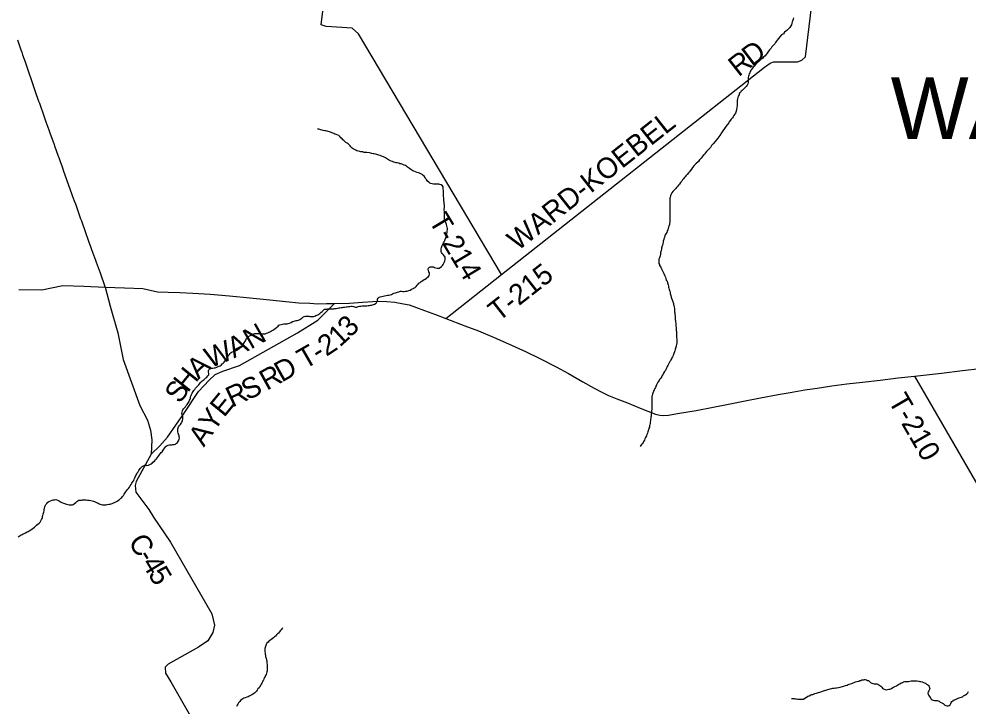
# Model space of a CAD drawing. Extents: x 1310247 to 1664935, y 284496 to 704931.
# Drawn here: x 1521928 to 1535762, y 510674 to 520692 of the extents above; entities that cross this region are included whole.
import ezdxf

# ---------------------------------------------------------------- set-up
doc = ezdxf.new("R2010")
doc.units = 0
for name, color, linetype in [('GM_X_Airport_Location_Class_2', 7, 'Continuous'), ('GM_X_County_Road_Text', 7, 'Continuous'), ('GM_X_County_Subdivision_Text', 7, 'Continuous'), ('GM_X_Interstate_Shield', 7, 'Continuous'), ('GM_X_Minor_River_Text', 7, 'Continuous'), ('GM_X_Township_Road', 7, 'Continuous'), ('GM_X_Township_Subdivision', 7, 'Continuous')]:
    doc.layers.add(name, color=color, linetype=linetype)

msp = doc.modelspace()

# ---------------------------------------------------------------- linework, layer by layer
at = {"layer": 'GM_X_County_Road_Text'}
msp.add_lwpolyline([(1521905, 520389), (1521936, 520301), (1521956, 520244), (1521969, 520208), (1521981, 520171), (1522016, 520068), (1522027, 520037), (1522150, 519680), (1522160, 519649), (1522166, 519633), (1522214, 519493), (1522225, 519462), (1522230, 519447), (1522285, 519292), (1522305, 519236), (1522321, 519193), (1522336, 519153), (1522362, 519076), (1522379, 519029), (1522440, 518860), (1522446, 518844), (1522501, 518690), (1522507, 518674), (1522523, 518628), (1522556, 518535), (1522578, 518473), (1522694, 518148), (1522705, 518118), (1522733, 518040), (1522750, 517994), (1522766, 517950), (1522827, 517778), (1522837, 517746), (1522897, 517576), (1522936, 517468), (1522941, 517453), (1522947, 517437), (1522969, 517376), (1522975, 517360), (1522986, 517329), (1523043, 517175), (1523048, 517160), (1523054, 517145), (1523110, 516990), (1523115, 516975), (1523121, 516959), (1523126, 516944), (1523165, 516835), (1523175, 516804), (1523181, 516789), (1523183, 516781), (1523257, 516502), (1523370, 516114), (1523445, 515726), (1523691, 515057), (1523801, 514842), (1523845, 514694), (1523863, 514553), (1523854, 514345), (1523636, 513947), (1523623, 513889), (1523632, 513792), (1523820, 513538), (1523888, 513429), (1524135, 513062), (1524739, 512018), (1524778, 511851), (1524756, 511745), (1524682, 511622), (1524545, 511533), (1524103, 511284), (1524057, 511238), (1524064, 511154), (1524141, 511025), (1525122, 509309)], dxfattribs=at)
at = {"layer": 'GM_X_County_Subdivision_Text'}
for points in [[(1528152, 516326), (1528963, 516966), (1532793, 519990), (1532878, 520049), (1532928, 520068), (1533275, 520069), (1533340, 520092), (1533395, 520141), (1533719, 522838), (1533986, 524929)], [(1528963, 516966), (1526878, 520477), (1526783, 520557), (1526408, 520580), (1526332, 520608), (1526811, 524451)], [(1523854, 514345), (1523982, 514468), (1524094, 514594), (1524337, 514944), (1524547, 515258), (1524701, 515427), (1524788, 515506), (1524901, 515555), (1525144, 515640), (1525987, 516117), (1526284, 516301), (1526525, 516541)], [(1534981, 515482), (1537007, 511984), (1537078, 511898), (1537141, 511835), (1537181, 511793), (1537242, 511641), (1537603, 511101)]]:
    msp.add_lwpolyline(points, dxfattribs=at)
at = {"layer": 'GM_X_Interstate_Shield'}
msp.add_lwpolyline([(1521927, 516748), (1522263, 516741), (1522566, 516806), (1522872, 516794), (1523183, 516781), (1523464, 516773), (1523734, 516764), (1523947, 516714), (1524104, 516708), (1524272, 516705), (1524464, 516693), (1524716, 516678), (1524996, 516653), (1525291, 516626), (1525583, 516595), (1525817, 516573), (1526009, 516555), (1526169, 516546), (1526282, 516540), (1526410, 516541), (1526525, 516541), (1526748, 516548), (1526933, 516562), (1527087, 516572), (1527175, 516577), (1527287, 516572), (1527407, 516563), (1527532, 516538), (1527616, 516521), (1527708, 516490), (1527839, 516439), (1527999, 516381), (1528152, 516326), (1528427, 516219), (1528628, 516145), (1528855, 516048), (1529064, 515956), (1529313, 515844), (1529522, 515742), (1529759, 515621), (1529936, 515523), (1530145, 515399), (1530312, 515306), (1530413, 515255), (1530519, 515203), (1530642, 515154), (1530796, 515095), (1530985, 515017), (1531206, 514931), (1531268, 514914), (1531322, 514909), (1531394, 514915), (1531528, 514937), (1531798, 514985), (1532045, 515032), (1532269, 515076), (1532489, 515118), (1532738, 515167), (1532994, 515217), (1533171, 515245), (1533385, 515283), (1533563, 515309), (1533779, 515343), (1533994, 515370), (1534224, 515394), (1534482, 515426), (1534742, 515457), (1534981, 515482), (1535377, 515528), (1535683, 515565), (1535938, 515595)], dxfattribs=at)
at = {"layer": 'GM_X_Minor_River_Text'}
for points in [[(1533220, 520710), (1533213, 520688), (1533205, 520662), (1533200, 520648), (1533196, 520630), (1533187, 520604), (1533179, 520590), (1533164, 520568), (1533144, 520548), (1533119, 520525), (1533088, 520497), (1533072, 520477), (1533045, 520458), (1533020, 520432), (1532998, 520406), (1532979, 520381), (1532964, 520363), (1532954, 520349), (1532944, 520329), (1532925, 520309), (1532902, 520284), (1532890, 520268), (1532869, 520240), (1532855, 520222), (1532836, 520192), (1532821, 520175), (1532805, 520155), (1532782, 520133), (1532770, 520119), (1532743, 520100), (1532712, 520070), (1532690, 520052), (1532669, 520031), (1532646, 520003), (1532632, 519989), (1532622, 519975), (1532603, 519952), (1532595, 519938), (1532586, 519924), (1532580, 519908), (1532573, 519894), (1532565, 519870), (1532561, 519856), (1532558, 519840), (1532558, 519820), (1532557, 519798), (1532555, 519778), (1532556, 519764), (1532552, 519744), (1532543, 519726), (1532527, 519706), (1532510, 519686), (1532490, 519666), (1532471, 519651), (1532457, 519639), (1532445, 519621), (1532428, 519603), (1532426, 519587), (1532413, 519565)], [(1532413, 519565), (1532405, 519545), (1532400, 519529), (1532396, 519501), (1532395, 519473), (1532396, 519455), (1532396, 519431), (1532393, 519401), (1532387, 519371), (1532382, 519349), (1532371, 519317), (1532357, 519297), (1532348, 519283), (1532338, 519265), (1532327, 519248), (1532311, 519230), (1532298, 519214), (1532282, 519190), (1532273, 519176), (1532249, 519149), (1532232, 519123), (1532211, 519093), (1532190, 519059), (1532169, 519029), (1532142, 518992), (1532115, 518956), (1532093, 518924), (1532076, 518905), (1532047, 518873), (1532037, 518859), (1532022, 518845), (1532008, 518819), (1531987, 518800), (1531969, 518778), (1531952, 518758), (1531931, 518735), (1531919, 518717), (1531902, 518699), (1531888, 518681), (1531871, 518663), (1531847, 518638), (1531832, 518612), (1531793, 518580), (1531770, 518553), (1531747, 518527), (1531729, 518503), (1531712, 518477), (1531700, 518464), (1531685, 518446), (1531669, 518424), (1531650, 518402), (1531638, 518388), (1531625, 518375), (1531613, 518361), (1531602, 518345), (1531588, 518327), (1531573, 518307), (1531557, 518285), (1531542, 518270), (1531526, 518250), (1531513, 518236), (1531501, 518220), (1531476, 518194), (1531460, 518177), (1531443, 518157), (1531430, 518129), (1531424, 518115), (1531418, 518093), (1531417, 518079), (1531417, 518055), (1531416, 518033), (1531416, 518009), (1531415, 517985), (1531415, 517957), (1531414, 517942), (1531416, 517914), (1531415, 517892), (1531415, 517874), (1531414, 517856), (1531416, 517840), (1531417, 517820), (1531417, 517806), (1531417, 517790), (1531414, 517774), (1531414, 517750), (1531413, 517732), (1531411, 517710), (1531409, 517696), (1531404, 517680), (1531398, 517660), (1531391, 517638), (1531385, 517618), (1531378, 517602), (1531370, 517580), (1531359, 517560), (1531349, 517542), (1531342, 517528), (1531336, 517506), (1531329, 517488), (1531327, 517474), (1531319, 517450)], [(1526925, 518752), (1526911, 518754), (1526895, 518759), (1526875, 518763), (1526855, 518771), (1526837, 518778), (1526821, 518790), (1526801, 518798), (1526787, 518809), (1526765, 518825), (1526754, 518840), (1526740, 518856), (1526724, 518870), (1526710, 518883), (1526694, 518891), (1526679, 518903), (1526663, 518918), (1526649, 518930), (1526637, 518946), (1526621, 518960), (1526604, 518979), (1526588, 518991), (1526566, 519000), (1526550, 519008), (1526534, 519012), (1526518, 519021), (1526502, 519027), (1526488, 519033), (1526470, 519040), (1526452, 519044), (1526434, 519050), (1526420, 519055), (1526400, 519059), (1526384, 519061), (1526364, 519066), (1526346, 519072), (1526328, 519076), (1526314, 519081), (1526298, 519083), (1526280, 519087)], [(1528170, 517654), (1528167, 517673), (1528161, 517693), (1528156, 517709), (1528152, 517723), (1528146, 517741), (1528141, 517757), (1528133, 517774), (1528133, 517792), (1528132, 517810), (1528130, 517824), (1528131, 517858), (1528129, 517872), (1528129, 517886), (1528128, 517902), (1528128, 517920), (1528129, 517943), (1528129, 517961), (1528129, 517979), (1528128, 518001), (1528124, 518019), (1528123, 518035), (1528121, 518051), (1528121, 518069), (1528120, 518085), (1528118, 518103), (1528118, 518117), (1528117, 518132), (1528117, 518148), (1528116, 518174), (1528116, 518192), (1528112, 518210), (1528111, 518224), (1528109, 518242), (1528100, 518260), (1528084, 518271), (1528064, 518279), (1528046, 518284), (1528026, 518284), (1528009, 518282), (1527991, 518283), (1527969, 518283), (1527949, 518287), (1527933, 518292), (1527917, 518298), (1527901, 518310), (1527882, 518327), (1527866, 518349), (1527854, 518367), (1527847, 518382), (1527833, 518400), (1527817, 518416), (1527801, 518429), (1527785, 518435), (1527767, 518441), (1527751, 518448), (1527731, 518454), (1527706, 518465), (1527686, 518471), (1527668, 518479), (1527654, 518488), (1527640, 518498), (1527622, 518510), (1527608, 518523), (1527590, 518533), (1527576, 518545), (1527563, 518554), (1527543, 518562), (1527525, 518568), (1527501, 518577), (1527481, 518581), (1527463, 518588), (1527439, 518592), (1527425, 518596), (1527411, 518600), (1527393, 518605), (1527371, 518611), (1527353, 518616), (1527333, 518626), (1527315, 518638), (1527301, 518647), (1527287, 518655), (1527269, 518665), (1527239, 518682), (1527225, 518688), (1527211, 518693), (1527195, 518699), (1527175, 518705), (1527159, 518710), (1527143, 518714), (1527127, 518718), (1527107, 518723), (1527091, 518727), (1527073, 518731), (1527057, 518734), (1527037, 518738), (1526997, 518745), (1526983, 518745), (1526961, 518747), (1526939, 518752), (1526925, 518752)], [(1527082, 516525), (1527098, 516527), (1527112, 516533), (1527133, 516549), (1527145, 516568), (1527152, 516586), (1527154, 516606), (1527165, 516620), (1527179, 516636), (1527193, 516642), (1527218, 516645), (1527236, 516649), (1527256, 516657), (1527278, 516658), (1527300, 516662), (1527321, 516664), (1527341, 516669), (1527359, 516675), (1527375, 516683), (1527392, 516694), (1527414, 516700), (1527445, 516710), (1527463, 516715), (1527477, 516719), (1527491, 516721), (1527505, 516723), (1527523, 516720), (1527541, 516720), (1527560, 516722), (1527574, 516721), (1527588, 516725), (1527612, 516731), (1527630, 516738), (1527651, 516750), (1527673, 516760), (1527689, 516769), (1527704, 516777), (1527718, 516793), (1527731, 516811), (1527747, 516823), (1527758, 516840), (1527774, 516850), (1527792, 516864), (1527815, 516880), (1527835, 516891), (1527849, 516899), (1527866, 516911), (1527880, 516923), (1527895, 516938), (1527905, 516952), (1527911, 516970), (1527910, 516988), (1527904, 517007), (1527899, 517023), (1527893, 517043), (1527897, 517057), (1527910, 517071), (1527924, 517076), (1527942, 517078), (1527956, 517078), (1527972, 517076), (1527986, 517069), (1528004, 517063), (1528022, 517057), (1528038, 517058), (1528052, 517060), (1528069, 517070), (1528087, 517084), (1528101, 517095), (1528112, 517111), (1528122, 517129), (1528131, 517149), (1528137, 517165), (1528142, 517183), (1528142, 517201), (1528140, 517217), (1528133, 517233), (1528111, 517258), (1528095, 517272), (1528086, 517286), (1528082, 517301), (1528080, 517319), (1528081, 517339), (1528085, 517359), (1528090, 517375), (1528098, 517389), (1528106, 517407), (1528115, 517426), (1528125, 517440), (1528136, 517460), (1528140, 517476), (1528145, 517490), (1528155, 517514), (1528162, 517536), (1528166, 517550), (1528166, 517566), (1528169, 517580), (1528171, 517600), (1528172, 517620), (1528172, 517636), (1528170, 517654)], [(1531319, 517450), (1531316, 517436), (1531312, 517418), (1531311, 517404), (1531305, 517384), (1531294, 517350), (1531294, 517336), (1531287, 517316), (1531281, 517284), (1531278, 517260), (1531274, 517238), (1531269, 517224), (1531263, 517210), (1531256, 517190), (1531254, 517174), (1531254, 517160), (1531255, 517144), (1531257, 517124), (1531263, 517110), (1531266, 517095), (1531282, 517073), (1531293, 517049), (1531303, 517031), (1531316, 516998), (1531328, 516980), (1531338, 516958), (1531351, 516929), (1531359, 516907), (1531364, 516885), (1531374, 516867), (1531381, 516842), (1531387, 516828), (1531391, 516814), (1531394, 516798), (1531398, 516780), (1531400, 516766), (1531407, 516745), (1531415, 516721), (1531419, 516705), (1531422, 516691), (1531426, 516675), (1531430, 516661), (1531437, 516634), (1531441, 516620), (1531450, 516598), (1531456, 516582), (1531467, 516543), (1531467, 516529), (1531473, 516513), (1531476, 516495), (1531482, 516463), (1531483, 516441), (1531485, 516423), (1531486, 516406), (1531490, 516386), (1531491, 516354), (1531495, 516340), (1531494, 516318), (1531499, 516276), (1531501, 516258), (1531501, 516243), (1531504, 516217), (1531508, 516189), (1531509, 516151), (1531510, 516137), (1531510, 516113), (1531511, 516095), (1531511, 516071), (1531512, 516048), (1531516, 516028), (1531516, 516014), (1531517, 515998), (1531515, 515962), (1531512, 515948), (1531508, 515920), (1531505, 515906), (1531492, 515870), (1531488, 515854), (1531482, 515836), (1531475, 515816), (1531469, 515800), (1531462, 515784), (1531454, 515766), (1531445, 515750), (1531439, 515736), (1531431, 515722), (1531424, 515709), (1531416, 515695), (1531405, 515677), (1531395, 515659), (1531385, 515641), (1531378, 515625), (1531370, 515611), (1531355, 515579), (1531351, 515565), (1531336, 515551), (1531322, 515528), (1531319, 515514), (1531305, 515494), (1531298, 515478), (1531282, 515456)], [(1525335, 516095), (1525349, 516101), (1525367, 516105), (1525383, 516107), (1525400, 516106), (1525416, 516106), (1525432, 516104), (1525448, 516101), (1525468, 516099), (1525486, 516101), (1525504, 516102), (1525518, 516102), (1525538, 516108), (1525557, 516115), (1525575, 516125), (1525595, 516135), (1525610, 516143), (1525628, 516154), (1525644, 516164), (1525663, 516178), (1525683, 516195), (1525704, 516211), (1525718, 516225), (1525732, 516231), (1525751, 516236), (1525769, 516240), (1525791, 516244), (1525819, 516245), (1525836, 516247), (1525852, 516249), (1525872, 516256), (1525894, 516268), (1525915, 516278), (1525935, 516285), (1525953, 516291), (1525969, 516293), (1525984, 516296), (1526004, 516302), (1526020, 516308), (1526034, 516318), (1526051, 516327), (1526067, 516345), (1526084, 516351), (1526102, 516357), (1526118, 516360), (1526134, 516360), (1526152, 516358), (1526170, 516353), (1526184, 516351), (1526202, 516353), (1526220, 516354), (1526239, 516360), (1526255, 516368), (1526269, 516372), (1526283, 516377), (1526298, 516387), (1526314, 516399), (1526328, 516411), (1526345, 516424), (1526363, 516442), (1526382, 516458), (1526396, 516460), (1526414, 516461), (1526428, 516463), (1526442, 516465), (1526459, 516465), (1526473, 516466), (1526501, 516466), (1526517, 516467), (1526533, 516469), (1526551, 516471), (1526569, 516475), (1526590, 516478), (1526606, 516480), (1526626, 516484), (1526642, 516485), (1526658, 516487), (1526673, 516491), (1526695, 516492), (1526711, 516496), (1526733, 516500), (1526749, 516501), (1526769, 516503), (1526784, 516505), (1526802, 516498), (1526820, 516492), (1526834, 516490), (1526854, 516491), (1526872, 516497), (1526894, 516503), (1526910, 516506), (1526931, 516508), (1526947, 516508), (1526965, 516509), (1526979, 516509), (1526999, 516509), (1527019, 516512), (1527037, 516516), (1527052, 516518), (1527066, 516520), (1527082, 516525)], [(1524242, 514685), (1524242, 514699), (1524243, 514713), (1524247, 514731), (1524253, 514745), (1524266, 514763), (1524280, 514777), (1524293, 514793), (1524299, 514807), (1524310, 514825), (1524312, 514839), (1524314, 514855), (1524317, 514869), (1524315, 514889), (1524311, 514907), (1524308, 514923), (1524304, 514939), (1524305, 514957), (1524313, 514977), (1524317, 514991), (1524326, 515005), (1524340, 515021), (1524353, 515037), (1524367, 515054), (1524378, 515070), (1524388, 515084), (1524400, 515100), (1524409, 515116), (1524415, 515132), (1524422, 515146), (1524426, 515162), (1524430, 515180), (1524437, 515200), (1524443, 515214), (1524452, 515234), (1524466, 515260), (1524475, 515275), (1524489, 515289), (1524502, 515307), (1524520, 515327), (1524535, 515341), (1524549, 515356), (1524564, 515374), (1524576, 515390), (1524588, 515406), (1524611, 515426), (1524625, 515437), (1524640, 515449), (1524654, 515461), (1524668, 515471), (1524683, 515487), (1524695, 515504), (1524696, 515523), (1524692, 515541), (1524689, 515559), (1524695, 515577), (1524711, 515591), (1524726, 515594), (1524742, 515598), (1524756, 515602), (1524774, 515605), (1524790, 515607), (1524811, 515613), (1524831, 515622), (1524845, 515630), (1524859, 515636), (1524874, 515646), (1524890, 515662), (1524905, 515671), (1524917, 515685), (1524929, 515701), (1524944, 515721), (1524956, 515737), (1524969, 515755), (1524979, 515778), (1524992, 515794), (1525004, 515812), (1525019, 515828), (1525035, 515838), (1525053, 515843), (1525072, 515849), (1525086, 515855), (1525102, 515863), (1525123, 515876), (1525139, 515884), (1525153, 515894), (1525170, 515908), (1525182, 515923), (1525192, 515939), (1525199, 515953), (1525209, 515967), (1525220, 515985), (1525228, 515999), (1525234, 516013), (1525245, 516027), (1525257, 516043), (1525272, 516058), (1525288, 516070), (1525302, 516078), (1525321, 516088), (1525335, 516095)], [(1531282, 515456), (1531267, 515436), (1531259, 515420), (1531242, 515397), (1531230, 515375), (1531223, 515359), (1531213, 515335), (1531204, 515317), (1531196, 515303), (1531187, 515283), (1531175, 515259), (1531166, 515237), (1531162, 515223), (1531157, 515201), (1531155, 515187), (1531154, 515171), (1531152, 515157), (1531152, 515133), (1531151, 515109), (1531153, 515091), (1531152, 515073), (1531152, 515055), (1531151, 515019), (1531151, 515000), (1531150, 514978), (1531148, 514962), (1531147, 514946), (1531145, 514928), (1531142, 514902), (1531140, 514886), (1531138, 514870), (1531135, 514852), (1531133, 514832), (1531130, 514814), (1531128, 514794), (1531123, 514776), (1531119, 514762), (1531117, 514740), (1531110, 514726), (1531104, 514702), (1531099, 514688), (1531095, 514670), (1531088, 514652), (1531082, 514632), (1531073, 514612), (1531061, 514588), (1531052, 514568), (1531044, 514548), (1531033, 514533), (1531025, 514517), (1531015, 514501), (1531004, 514487), (1530994, 514473), (1530981, 514457)], [(1522905, 513679), (1522929, 513677), (1522953, 513674), (1522975, 513668), (1522995, 513665), (1523013, 513659), (1523029, 513655), (1523047, 513648), (1523067, 513638), (1523081, 513630), (1523097, 513623), (1523111, 513617), (1523127, 513613), (1523143, 513608), (1523161, 513608), (1523181, 513608), (1523197, 513608), (1523215, 513611), (1523239, 513615), (1523258, 513618), (1523274, 513622), (1523288, 513628), (1523304, 513634), (1523319, 513639), (1523339, 513649), (1523361, 513663), (1523380, 513676), (1523394, 513686), (1523413, 513704), (1523427, 513716), (1523437, 513730), (1523450, 513743), (1523460, 513761), (1523469, 513777), (1523481, 513793), (1523496, 513811), (1523506, 513825), (1523523, 513847), (1523537, 513864), (1523549, 513882), (1523564, 513902), (1523575, 513922), (1523585, 513936), (1523593, 513950), (1523600, 513964), (1523608, 513980), (1523617, 514000), (1523623, 514014), (1523631, 514029), (1523638, 514043), (1523644, 514057), (1523652, 514073), (1523663, 514089), (1523675, 514107), (1523686, 514123), (1523696, 514139), (1523709, 514153), (1523725, 514166), (1523743, 514178), (1523762, 514184), (1523780, 514185), (1523794, 514183), (1523814, 514187), (1523834, 514194), (1523855, 514206), (1523869, 514214), (1523881, 514230), (1523902, 514245), (1523916, 514263), (1523931, 514277), (1523945, 514297), (1523962, 514317), (1523972, 514333), (1523985, 514350), (1524001, 514368), (1524014, 514382), (1524028, 514402), (1524041, 514418), (1524053, 514436), (1524064, 514451), (1524072, 514465), (1524088, 514473), (1524102, 514477), (1524123, 514480), (1524139, 514482), (1524157, 514482), (1524173, 514486), (1524189, 514487), (1524208, 514493), (1524226, 514505), (1524238, 514518), (1524251, 514538), (1524259, 514552), (1524264, 514566), (1524266, 514582), (1524264, 514596), (1524261, 514612), (1524253, 514637), (1524249, 514653), (1524244, 514671), (1524242, 514685)], [(1521916, 513143), (1521930, 513151), (1521945, 513158), (1521961, 513170), (1521975, 513176), (1521990, 513184), (1522004, 513189), (1522024, 513201), (1522045, 513213), (1522063, 513220), (1522077, 513230), (1522102, 513242), (1522116, 513252), (1522136, 513267), (1522153, 513281), (1522167, 513295), (1522184, 513309), (1522204, 513326), (1522221, 513340), (1522235, 513356), (1522248, 513374), (1522258, 513392), (1522266, 513410), (1522269, 513424), (1522273, 513438), (1522278, 513454), (1522282, 513472), (1522286, 513488), (1522289, 513502), (1522293, 513518), (1522295, 513536), (1522298, 513558), (1522305, 513580), (1522311, 513594), (1522321, 513613), (1522334, 513627), (1522348, 513647), (1522363, 513657), (1522385, 513667), (1522411, 513674), (1522428, 513678), (1522448, 513681), (1522466, 513683), (1522482, 513679), (1522502, 513668), (1522520, 513660), (1522534, 513652), (1522552, 513643), (1522576, 513633), (1522590, 513629), (1522607, 513622), (1522621, 513618), (1522639, 513612), (1522659, 513607), (1522674, 513605), (1522688, 513605), (1522706, 513608), (1522720, 513614), (1522736, 513626), (1522755, 513642), (1522771, 513655), (1522788, 513667), (1522802, 513675), (1522818, 513677), (1522840, 513676), (1522854, 513678), (1522876, 513678), (1522891, 513679), (1522905, 513679)], [(1525772, 511815), (1525759, 511797), (1525749, 511783), (1525736, 511769), (1525724, 511755), (1525710, 511738), (1525697, 511724), (1525683, 511710), (1525666, 511694), (1525652, 511682), (1525636, 511669), (1525617, 511655), (1525601, 511641), (1525586, 511629), (1525572, 511620), (1525558, 511606), (1525543, 511588), (1525533, 511572), (1525526, 511556), (1525520, 511542), (1525518, 511528), (1525513, 511512), (1525513, 511494), (1525513, 511480), (1525512, 511462), (1525516, 511444), (1525517, 511430), (1525519, 511414), (1525523, 511396), (1525526, 511379), (1525530, 511365), (1525536, 511349), (1525539, 511333), (1525543, 511313), (1525543, 511297), (1525546, 511279), (1525546, 511265), (1525548, 511251), (1525547, 511232), (1525547, 511218), (1525545, 511204), (1525544, 511186), (1525542, 511170), (1525537, 511152), (1525531, 511134), (1525522, 511118), (1525516, 511104), (1525508, 511089), (1525499, 511071), (1525491, 511053), (1525482, 511039), (1525476, 511025), (1525466, 511007), (1525457, 510991), (1525449, 510973), (1525438, 510957), (1525430, 510937), (1525411, 510922), (1525399, 510904), (1525390, 510890), (1525378, 510876), (1525360, 510862), (1525337, 510847), (1525323, 510839), (1525302, 510825), (1525284, 510815), (1525268, 510810), (1525248, 510802), (1525227, 510794), (1525205, 510787), (1525191, 510777), (1525176, 510771), (1525158, 510755), (1525145, 510740), (1525129, 510720), (1525116, 510702), (1525108, 510686), (1525100, 510666)], [(1533189, 510781), (1533208, 510785), (1533226, 510782), (1533242, 510780), (1533258, 510778), (1533280, 510775), (1533294, 510773), (1533314, 510773), (1533330, 510772), (1533348, 510774), (1533364, 510776), (1533381, 510786), (1533409, 510803), (1533426, 510815), (1533448, 510824), (1533470, 510836), (1533487, 510840), (1533501, 510844), (1533531, 510855), (1533552, 510861), (1533568, 510866), (1533584, 510870), (1533602, 510878), (1533616, 510882), (1533653, 510893), (1533671, 510901), (1533691, 510906), (1533716, 510914), (1533738, 510920), (1533754, 510923), (1533775, 510929), (1533789, 510933), (1533811, 510934), (1533835, 510938), (1533849, 510940), (1533873, 510943), (1533896, 510947), (1533930, 510958), (1533952, 510964), (1533977, 510973), (1533999, 510979), (1534015, 510987), (1534030, 510993), (1534068, 511004), (1534088, 511012), (1534103, 511017), (1534121, 511025), (1534143, 511031), (1534170, 511038), (1534186, 511044), (1534200, 511048), (1534216, 511055), (1534236, 511057), (1534251, 511059), (1534265, 511059), (1534281, 511054), (1534295, 511048), (1534309, 511044), (1534326, 511029), (1534340, 511017), (1534358, 511009), (1534376, 511000), (1534392, 510998), (1534410, 510996), (1534432, 510995), (1534446, 510991), (1534460, 510985), (1534474, 510972), (1534490, 510964), (1534504, 510950), (1534517, 510935), (1534531, 510923), (1534555, 510915), (1534571, 510912), (1534587, 510914), (1534606, 510918), (1534622, 510919), (1534636, 510925), (1534652, 510935), (1534677, 510947), (1534697, 510956), (1534720, 510970), (1534736, 510980), (1534750, 510987), (1534767, 510999), (1534789, 511011), (1534807, 511018), (1534823, 511024), (1534842, 511030), (1534856, 511030), (1534876, 511031), (1534894, 511033), (1534916, 511037), (1534931, 511040), (1534949, 511040), (1534967, 511040), (1534983, 511039), (1535003, 511039), (1535017, 511039), (1535043, 511036), (1535059, 511032)], [(1535059, 511032), (1535075, 511030), (1535093, 511025), (1535113, 511019), (1535129, 511013), (1535143, 511006), (1535159, 510994), (1535175, 510984), (1535191, 510971), (1535196, 510955), (1535202, 510941), (1535204, 510927), (1535199, 510913), (1535189, 510897), (1535179, 510879), (1535178, 510861), (1535182, 510847), (1535191, 510829), (1535199, 510814), (1535211, 510800), (1535221, 510786), (1535226, 510772), (1535240, 510763), (1535254, 510757), (1535272, 510753), (1535290, 510753), (1535311, 510752), (1535327, 510748), (1535340, 510742), (1535358, 510731), (1535382, 510719), (1535398, 510708), (1535412, 510698), (1535426, 510686), (1535440, 510681), (1535458, 510675), (1535474, 510675), (1535488, 510681), (1535502, 510690), (1535513, 510708), (1535517, 510724), (1535528, 510740), (1535542, 510750), (1535562, 510762), (1535579, 510771), (1535601, 510779), (1535619, 510789), (1535634, 510792), (1535648, 510796), (1535666, 510804), (1535680, 510810), (1535697, 510821), (1535713, 510831), (1535727, 510837), (1535746, 510851), (1535758, 510868), (1535768, 510884)]]:
    msp.add_lwpolyline(points, dxfattribs=at)

# ---------------------------------------------------------------- texts
at = {"layer": 'GM_X_Airport_Location_Class_2'}
msp.add_text('WASHINGTON', height=900, rotation=0, dxfattribs=at).set_placement((1534635, 518940))
at = {"layer": 'GM_X_Township_Road'}
for s, rotation, p in [('C', 302.6541, (1523512, 513066)), ('-', 301.6612, (1523644, 512860)), ('4', 301.0075, (1523708, 512756)), ('5', 300.513, (1523803, 512598))]:
    msp.add_text(s, height=300, rotation=rotation, dxfattribs=at).set_placement(p)
at = {"layer": 'GM_X_Township_Subdivision'}
for s, rotation, p in [('D', 37.1475, (1532610, 519990)), ('R', 38.0947, (1532417, 519839)), ('WARD-KOEBEL', 38.2942, (1529196, 517300)), ('T-214', 300.9632, (1527894, 517749)), ('T-215', 38.047, (1528917, 516269)), ('3', 45.1805, (1526752, 516033)), ('N', 29.6975, (1525306, 515868)), ('1', 42.4489, (1526605, 515898)), ('W', 22.4102, (1524713, 515595)), ('A', 27.5614, (1525061, 515740)), ('2', 33.1902, (1526408, 515764)), ('T', 29.8326, (1526092, 515578)), ('-', 31.4956, (1526295, 515695)), ('A', 43.3022, (1524545, 515429)), ('D', 29.4272, (1525758, 515388)), ('H', 51.1809, (1524387, 515232)), ('R', 29.0103, (1525540, 515267)), ('S', 25.2245, (1525256, 515127)), ('S', 55.2345, (1524275, 515070)), ('R', 24.9992, (1525032, 515023)), ('E', 50.6367, (1524917, 514871)), ('T-210', 300.0947, (1534592, 515125)), ('Y', 55.2652, (1524771, 514659)), ('A', 55.7371, (1524623, 514441))]:
    msp.add_text(s, height=300, rotation=rotation, dxfattribs=at).set_placement(p)

doc.saveas('drawing.dxf')
